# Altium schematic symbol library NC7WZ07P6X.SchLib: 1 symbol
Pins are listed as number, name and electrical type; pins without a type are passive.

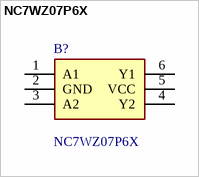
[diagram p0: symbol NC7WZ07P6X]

## NC7WZ07P6X
designator B?
Over-Voltage Tolerant Inputs Facilitate 5V to 3V Translation ; Ultra-Small MicroPak Packages; Proprietay Noise/EMI Reduction Circuitry ; Ultra-High Speed: tPZL 2.3ns (Typical) ; Power Down High Iimpedance Inputs/Outputs ; High IOL Output Drive: +24mA at 3V VCC ; Broad VCC Operating Range: 1.65V to 5.5V; Manufacturer_Name: onsemi; Geometry.Height: 1.1mm
footprint SOT65P210X110-6N
pins: 1 A1, 2 GND, 3 A2, 4 Y2, 5 VCC, 6 Y1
